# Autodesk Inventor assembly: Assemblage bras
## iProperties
Created: 2011-02
Part Number: Assemblage bras
Document SubType Name: Assembly
Designer: eric
Norme de conversion: IGES 5.3
Nom du fichier: No Iges File Name specified
Préprocesseur: Autodesk Inventor 2011
Postprocesseur: Build: 342, Release: 2008 SP3 - Date: Tue 05/27/2008
Unités envoyées: MM
Incertitude: 0.01
Author: eric
